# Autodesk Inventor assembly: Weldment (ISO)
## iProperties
Length Units: 11269
Angle Units: 11283
Time Units: 11279
Mass Units: 11290
Length Display Precision: 3
Angle Display Precision: 2
Part Number: Weldment (ISO)
Document SubType Name: Weldment
Created: 2002-06
Designer: smithga
Part Number: Ens_reduction
Created: 2008-02
Designer: Pascal
Material: Aluminum soudé-6061
Control State: 0
Master: False
Shininess: 64.0
Angle Units: 11279
Time Units: 11290
Mass Units: 11283
Compacted: True
DESIGNATION: Ensemble réduction entrée/sortie
Density: 0.0
Volumn: 0.0
Area: 0.0
PropertySet Name: Model Information
Author: Pascal
